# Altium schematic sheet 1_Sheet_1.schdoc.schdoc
size 495 x 241 mm; Name: A_A4; Symbol: A_A4; Device: A_A4; @Project Name: pupnik_2023-12-26_01-16-22; REV: 1.0; Date: 2023-12-25; Sheet: 1/1; Draw By: Penguin Kothe; Company: Your Company; Convert to PCB: yes; Add into BOM: yes
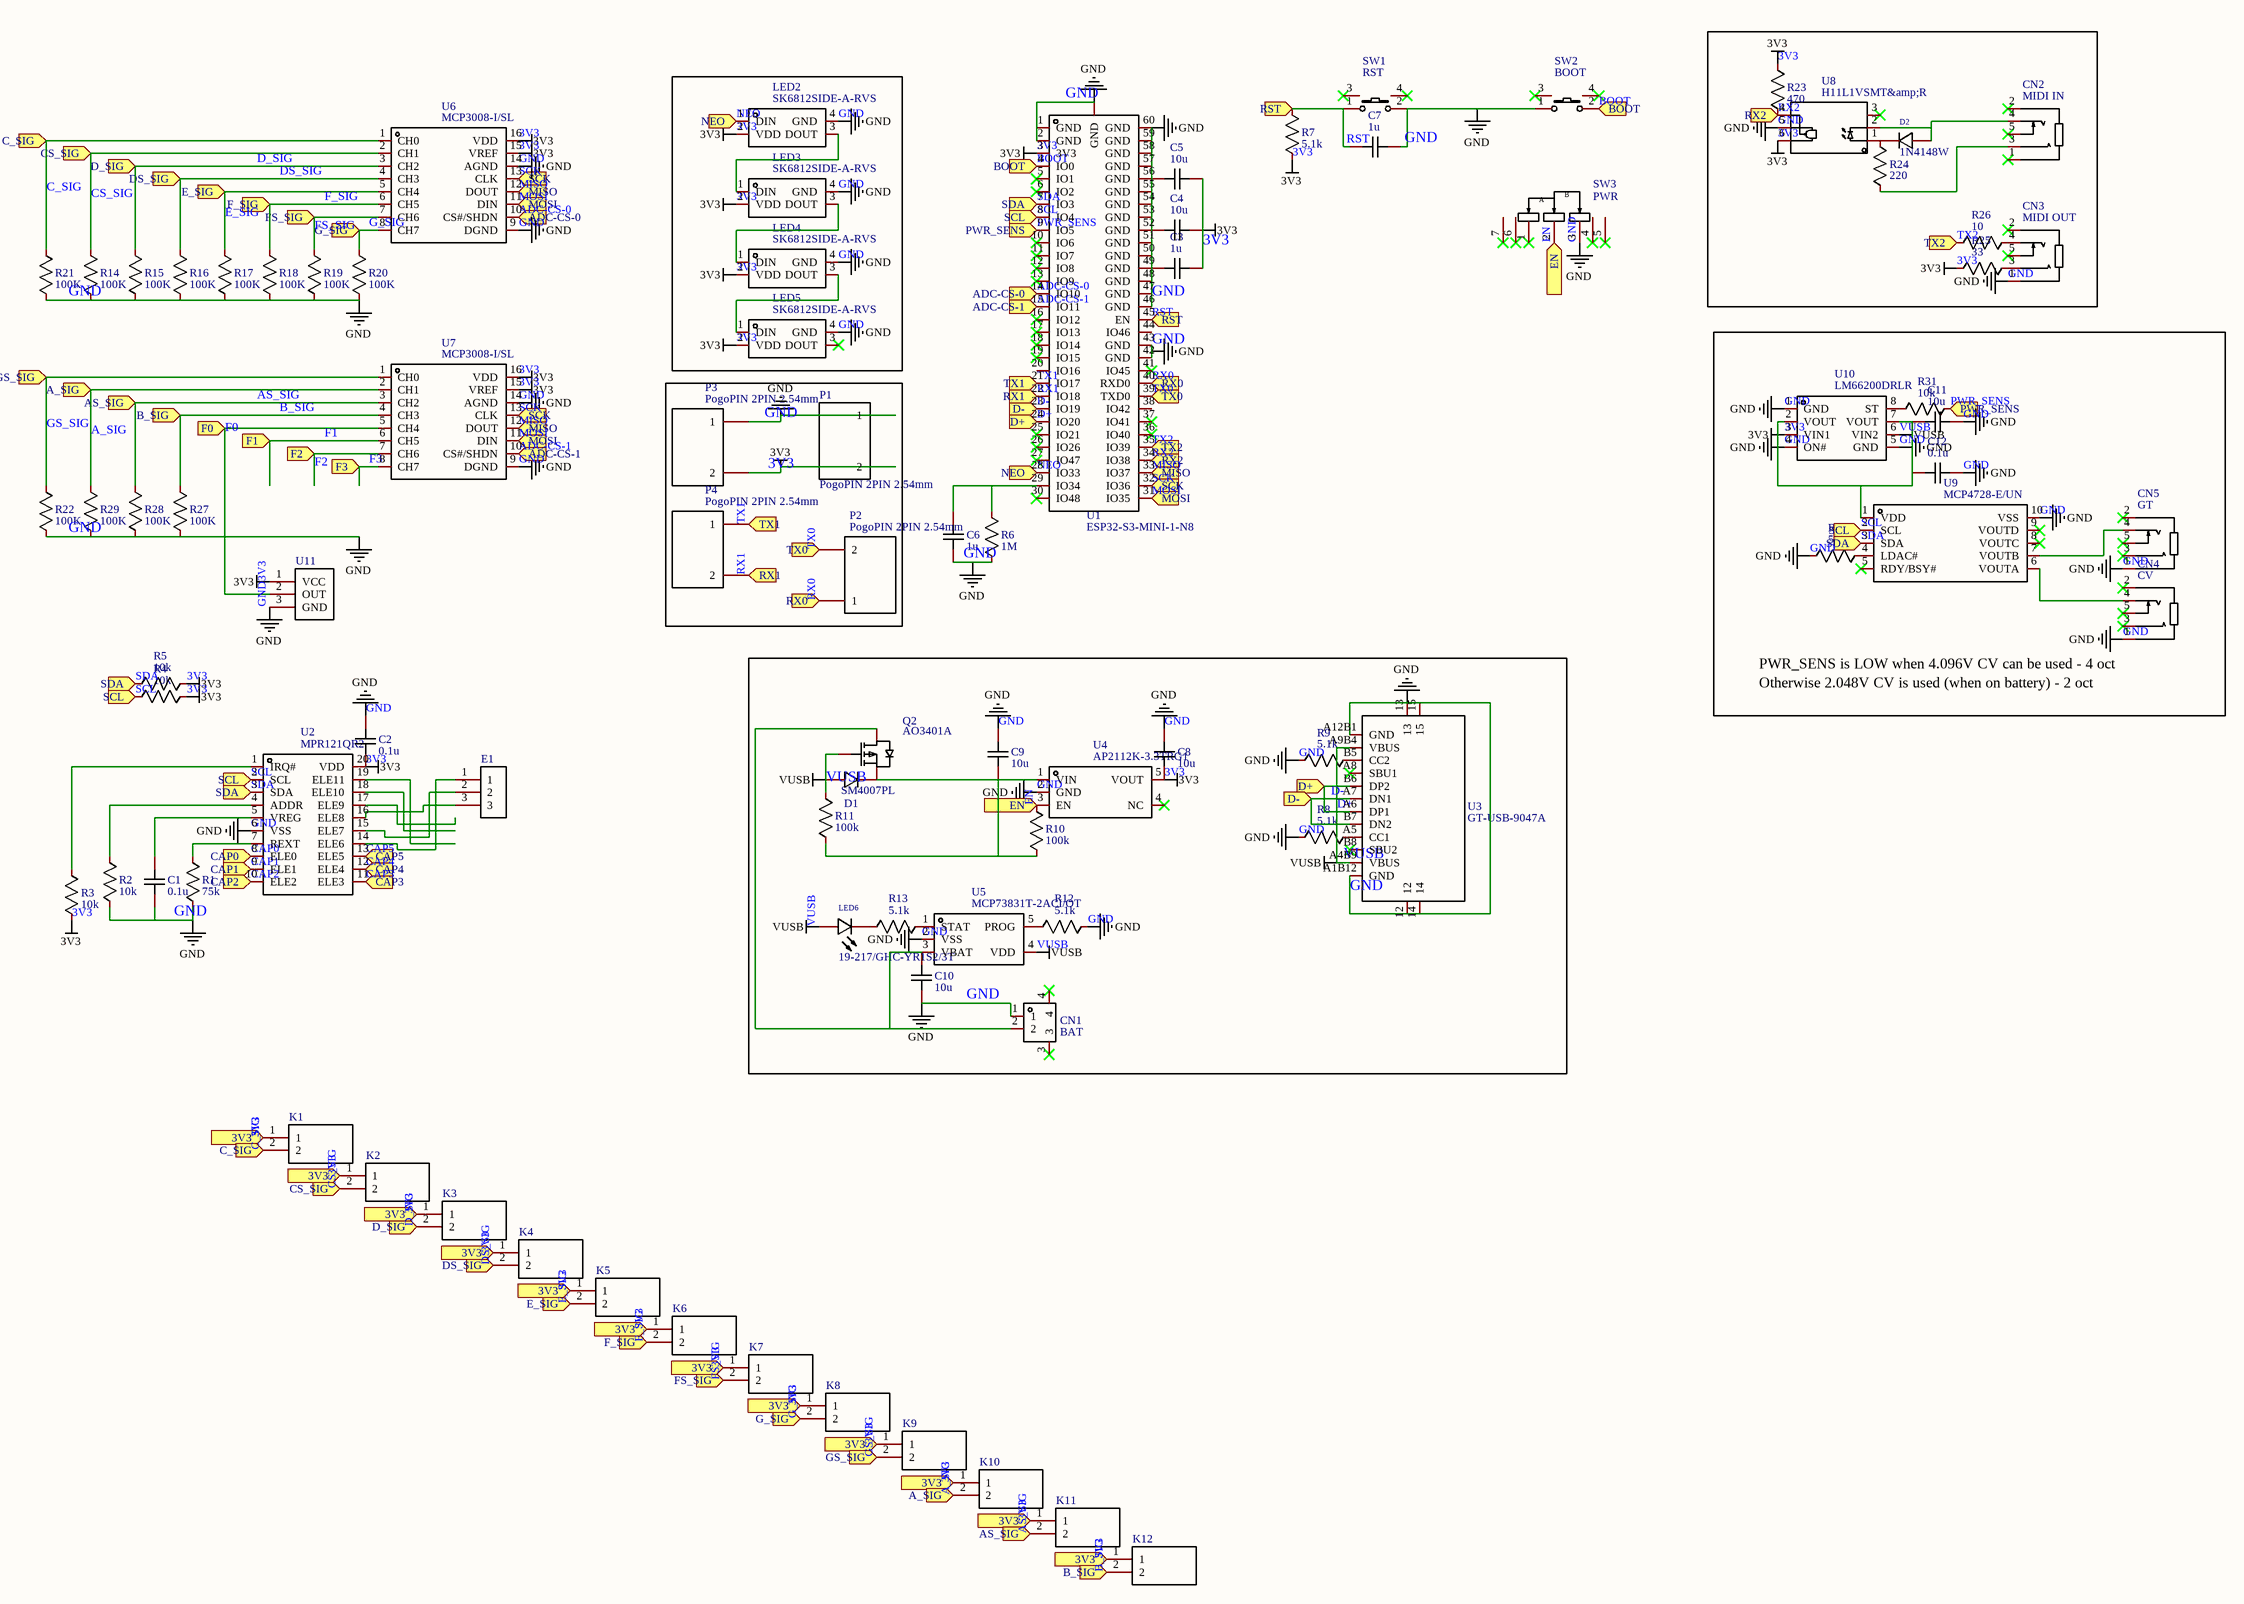
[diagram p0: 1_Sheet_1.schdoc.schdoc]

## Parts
C1  0.1u  [C0603]
C2  0.1u  [C0603]
C3  1u  [C0603]
C4  10u  [C0603]
C5  10u  [C0603]
C6  1u  [C0603]
C7  1u  [C0603]
C8  10u  [C0603]
C9  10u  [C0603]
C10  10u  [C0603]
C11  10u  [C0603]
C12  0.1u  [C0603]
CN1  BAT  [CONN-SMD_P2.00_S2B-PH-SM4-TB-LF-SN]
CN2  MIDI IN  [AUDIO-SMD_PJ-327A5JJ]
CN3  MIDI OUT  [AUDIO-SMD_PJ-327A5JJ]
CN4  CV  [AUDIO-SMD_PJ-327A5JJ]
CN5  GT  [AUDIO-SMD_PJ-327A5JJ]
D1  SM4007PL  [SOD-123F_L2.8-W1.8-LS3.7-RD]
D2  1N4148W  [SOD-123F_L2.7-W1.6-LS3.8-RD]
E1  enc  [enc]  (value not drawn)
K1  key  [key]  (value not drawn)
K2  key  [key]  (value not drawn)
K3  key  [key]  (value not drawn)
K4  key  [key]  (value not drawn)
K5  key  [key]  (value not drawn)
K6  key  [key]  (value not drawn)
K7  key  [key]  (value not drawn)
K8  key  [key]  (value not drawn)
K9  key  [key]  (value not drawn)
K10  key  [key]  (value not drawn)
K11  key  [key]  (value not drawn)
K12  key  [key]  (value not drawn)
LED2  SK6812SIDE-A-RVS  [LED-SMD_4P-L4.0-W1.6-L]
LED3  SK6812SIDE-A-RVS  [LED-SMD_4P-L4.0-W1.6-L]
LED4  SK6812SIDE-A-RVS  [LED-SMD_4P-L4.0-W1.6-L]
LED5  SK6812SIDE-A-RVS  [LED-SMD_4P-L4.0-W1.6-L]
LED6  19-217/GHC-YR1S2/3T  [LED0603-RD]
P1  PogoPIN 2PIN 2.54mm  [POGOPIN 2PIN 2.5MM]
P2  PogoPIN 2PIN 2.54mm  [POGOPIN 2PIN 2.5MM]
P3  PogoPIN 2PIN 2.54mm  [POGOPIN 2PIN 2.5MM]
P4  PogoPIN 2PIN 2.54mm  [POGOPIN 2PIN 2.5MM]
Q2  AO3401A  [SOT-23_L2.9-W1.3-P1.90-LS2.4-BR]
R1  75k  [R0603]
R2  10k  [R0603]
R3  10k  [R0603]
R4  10k  [R0603]
R5  10k  [R0603]
R6  1M  [R0603]
R7  5.1k  [R0603]
R8  5.1k  [R0603]
R9  5.1k  [R0603]
R10  100k  [R0603]
R11  100k  [R0603]
R12  5.1k  [R0603]
R13  5.1k  [R0603]
R14  100K  [R0603]
R15  100K  [R0603]
R16  100K  [R0603]
R17  100K  [R0603]
R18  100K  [R0603]
R19  100K  [R0603]
R20  100K  [R0603]
R21  100K  [R0603]
R22  100K  [R0603]
R23  470  [R0603]
R24  220  [R0603]
R25  33  [R0603]
R26  10  [R0603]
R27  100K  [R0603]
R28  100K  [R0603]
R29  100K  [R0603]
R30  5.1k  [R0603]
R31  10k  [R0603]
SW1  RST  [SW-SMD_L4.7-W3.5-P3.35-EH]
SW2  BOOT  [SW-SMD_L4.7-W3.5-P3.35-EH]
SW3  PWR  [SW-SMD_MK-12C02-G020]
U1  ESP32-S3-MINI-1-N8  [BULETM-SMD_ESP32-S3-MINI-1-N8]
U2  MPR121QR2  [QFN-20_L3.0-W3.0-P0.40-BL]
U3  GT-USB-9047A  [USB-C-SMD_GT-USB-9047A]
U4  AP2112K-3.3TRG1  [SOT-25-5_L2.9-W1.6-P0.95-LS2.8-BL]
U5  MCP73831T-2ACI/OT  [SOT-23-5_L3.0-W1.7-P0.95-LS2.8-BL]
U6  MCP3008-I/SL  [SOIC-16_L9.9-W3.9-P1.27-LS6.0-BL]
U7  MCP3008-I/SL  [SOIC-16_L9.9-W3.9-P1.27-LS6.0-BL]
U8  H11L1VSMT&amp;R  [SMD-6_L8.6-W6.4-P2.54-LS9.4-BL]
U9  MCP4728-E/UN  [MSOP-10_L3.0-W3.0-P0.50-LS5.0-TL]
U10  LM66200DRLR  [SOT-583-8_L2.1-W1.2-P0.50-LS1.6-BL]
U11  farts  [farts]  (value not drawn)

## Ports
3V3 (in), A_SIG (in), ADC-CS-0 (in), ADC-CS-1 (in), AS_SIG (in), B_SIG (in), BOOT (in), C_SIG (in), CAP0 (in), CAP1 (in), CAP2 (in), CAP3 (in), CAP4 (in), CAP5 (in), CS_SIG (in), D+ (in), D- (in), D_SIG (in), DS_SIG (in), E_SIG (in), EN (in), F0 (in), F1 (in), F2 (in), F3 (in), F_SIG (in), FS_SIG (in), G_SIG (in), GS_SIG (in), MISO (in), MOSI (in), NEO (in), PWR_SENS (in), RST (in), RX0 (in), RX1 (in), RX2 (in), SCK (in), SCL (in), SDA (in), TX0 (in), TX1 (in), TX2 (in)

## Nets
3V3: C2.1 C3.2 C4.2 C5.2 C8.1 K1.1 K2.1 K3.1 K4.1 K5.1 K6.1 K7.1 K8.1 K9.1 K10.1 K11.1 K12.1 LED2.2(VDD) LED3.2(VDD) LED4.2(VDD) LED5.2(VDD) P1.2 P3.2 R3.1 R4.1 R5.1 R7.1 R23.2 R25.2 U1.3(3V3) U2.20(VDD) U4.5(VOUT) U6.15(VREF) U6.16(VDD) U7.15(VREF) U7.16(VDD) U8.6(VCC) U10.3(VIN1) U11.1(VCC) ; port 3V3
D+: D1.2(A) LED6.2(A) Q2.1(G) R11.2 U1.24(IO20) U3.A4B9(VBUS) U3.A6(DP1) U3.A9B4(VBUS) U3.B6(DP2) U5.4(VDD) U10.6(VIN2) ; port D+  [also labelled VUSB]
GND: C1.1 C2.2 C3.1 C4.1 C5.1 C6.1 C7.2 C8.2 C9.2 C10.1 C11.1 C12.1 CN1.1 CN3.1 CN4.1 CN5.1 LED2.4(GND) LED3.4(GND) LED4.4(GND) LED5.4(GND) P1.1 P3.1 R1.1 R2.1 R6.1 R8.1 R9.1 R12.2 R14.1 R15.1 R16.1 R17.1 R18.1 R19.1 R20.1 R21.1 R22.1 R27.1 R28.1 R29.1 R30.1 SW1.2 SW2.1 SW3.3 U1.1(GND) U1.2(GND) U1.42(GND) U1.43(GND) U1.46(GND) U1.47(GND) U1.48(GND) U1.49(GND) U1.50(GND) U1.51(GND) U1.52(GND) U1.53(GND) U1.54(GND) U1.55(GND) U1.56(GND) U1.57(GND) U1.58(GND) U1.59(GND) U1.60(GND) U1.GND U2.6(VSS) U3.12 U3.13 U3.14 U3.15 U3.A1B12(GND) U3.A12B1(GND) U4.2(GND) U5.2(VSS) U6.9(DGND) U6.14(AGND) U7.9(DGND) U7.14(AGND) U8.5(GND) U9.10(VSS) U10.1(GND) U10.4(ON#) U10.5(GND) U11.3(GND)
A_SIG: K10.2 R29.2 U7.2(CH1) ; port A_SIG
ADC-CS-0: U1.14(IO10) U6.10(CS#/SHDN) ; port ADC-CS-0
ADC-CS-1: U1.15(IO11) U7.10(CS#/SHDN) ; port ADC-CS-1
AS_SIG: K11.2 R28.2 U7.3(CH2) ; port AS_SIG
B_SIG: K12.2 R27.2 U7.4(CH3) ; port B_SIG
BOOT: SW2.2 U1.4(IO0) ; port BOOT
C_SIG: K1.2 R21.2 U6.1(CH0) ; port C_SIG
CAP0: U2.8(ELE0) ; port CAP0
CAP1: U2.9(ELE1) ; port CAP1
CAP2: U2.10(ELE2) ; port CAP2
CAP3: U2.11(ELE3) ; port CAP3
CAP4: U2.12(ELE4) ; port CAP4
CAP5: U2.13(ELE5) ; port CAP5
CS_SIG: K2.2 R14.2 U6.2(CH1) ; port CS_SIG
D-: U1.23(IO19) U3.A7(DN1) U3.B7(DN2) ; port D-
D_SIG: K3.2 R15.2 U6.3(CH2) ; port D_SIG
DS_SIG: K4.2 R16.2 U6.4(CH3) ; port DS_SIG
E_SIG: K5.2 R17.2 U6.5(CH4) ; port E_SIG
EN: R10.2 SW3.2 U4.3(EN) ; port EN
F0: U7.5(CH4) U11.2(OUT) ; port F0
F1: U7.6(CH5) ; port F1
F2: U7.7(CH6) ; port F2
F3: U7.8(CH7) ; port F3
F_SIG: K6.2 R18.2 U6.6(CH5) ; port F_SIG
FS_SIG: K7.2 R19.2 U6.7(CH6) ; port FS_SIG
G_SIG: K8.2 R20.2 U6.8(CH7) ; port G_SIG
GS_SIG: K9.2 R22.2 U7.1(CH0) ; port GS_SIG
MISO: U1.33(IO37) U6.12(DOUT) U7.12(DOUT) ; port MISO
MOSI: U1.31(IO35) U6.11(DIN) U7.11(DIN) ; port MOSI
NEO: LED2.1(DIN) U1.28(IO33) ; port NEO
PWR_SENS: R31.2 U1.9(IO5) ; port PWR_SENS
RST: C7.1 R7.2 SW1.1 U1.45(EN) ; port RST
RX0: P2.1 U1.40(RXD0) ; port RX0
RX1: P4.2 U1.22(IO18) ; port RX1
RX2: R23.1 U1.34(IO38) U8.4(VO) ; port RX2
SCK: U1.32(IO36) U6.13(CLK) U7.13(CLK) ; port SCK
SCL: R4.2 U1.8(IO4) U2.2(SCL) U9.2(SCL) ; port SCL
SDA: R5.2 U1.7(IO3) U2.3(SDA) U9.3(SDA) ; port SDA
TX0: P2.2 U1.39(TXD0) ; port TX0
TX1: P4.1 U1.21(IO17) ; port TX1
TX2: R26.2 U1.35(IO39) ; port TX2
NetC1_2: C1.2 U2.5(VREG)
NetC6_2: C6.2 R6.2 U1.29(IO34)
NetC9_1: C9.1 D1.1(C) Q2.2(S) R10.1 R11.1 U4.1(VIN)
NetC10_2: C10.2 CN1.2 Q2.3(D) U5.3(VBAT)
NetC11_2: C11.2 C12.2 U9.1(VDD) U10.2(VOUT) U10.7(VOUT)
NetCN2_3: CN2.3 R24.1
NetCN2_4: CN2.4 D2.2(A) U8.2(C)
NetCN3_3: CN3.3 R25.1
NetCN3_4: CN3.4 R26.1
NetCN4_4: CN4.4 U9.6(VOUTA)
NetCN5_4: CN5.4 U9.7(VOUTB)
NetD2_1: D2.1(K) R24.2 U8.1(A)
NetE1_1: E1.1 U2.14(ELE6)
NetE1_2: E1.2 U2.15(ELE7)
NetE1_3: E1.3 U2.16(ELE8)
NetLED2_3: LED2.3(DOUT) LED3.1(DIN)
NetLED3_3: LED3.3(DOUT) LED4.1(DIN)
NetLED4_3: LED4.3(DOUT) LED5.1(DIN)
NetLED6_1: LED6.1(C) R13.1
NetR1_2: R1.2 U2.7(REXT)
NetR2_2: R2.2 U2.4(ADDR)
NetR3_2: R3.2 U2.1(IRQ#)
NetR8_2: R8.2 U3.A5(CC1)
NetR9_2: R9.2 U3.B5(CC2)
NetR12_1: R12.1 U5.5(PROG)
NetR13_2: R13.2 U5.1(STAT)
NetR30_2: R30.2 U9.4(LDAC#)
NetR31_1: R31.1 U10.8(ST)

Not connected (* = marked no-connect by the designer): CN1 3* 4*; CN2 1* 2* 5*; CN3 2* 5*; CN4 2* 3* 5*; CN5 2* 3* 5*; LED5 3(DOUT)*; SW1 3* 4*; SW2 3* 4*; SW3 1* 4* 5* 6* 7*; U1 5(IO1)* 6(IO2)* 10(IO6)* 11(IO7)* 12(IO8)* 13(IO9)* 16(IO12)* 17(IO13)* 18(IO14)* 19(IO15)* 20(IO16) 25(IO21)* 26(IO26)* 27(IO47)* 30(IO48)* 36(IO40)* 37(IO41)* 38(IO42) 41(IO45)* 44(IO46); U2 17(ELE9) 18(ELE10) 19(ELE11); U3 A8(SBU1)* B8(SBU2)*; U4 4(NC)*; U8 3(NC)*; U9 5(RDY/BSY#)* 8(VOUTC)* 9(VOUTD)*

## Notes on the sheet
- (near CN4) PWR_SENS is LOW when 4.096V CV can be used - 4 oct
- (near CN4) Otherwise 2.048V CV is used (when on battery) - 2 oct

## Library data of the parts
C1 C2 C12 = 0.1u: Convert to PCB: yes
C3 C6 C7 = 1u: Convert to PCB: yes
C4 C5 C8-C11 = 10u: Convert to PCB: yes
CN1 = BAT: Manufacturer: JST; Manufacturer Part: S2B-PH-SM4-TB(LF)(SN); Convert to PCB: yes
CN2 = MIDI IN: Manufacturer: SHOU HAN(首韩); Manufacturer Part: PJ-327A 5JJ; Convert to PCB: yes
CN3 = MIDI OUT: Manufacturer: SHOU HAN(首韩); Manufacturer Part: PJ-327A 5JJ; Convert to PCB: yes
CN4 = CV: Manufacturer: SHOU HAN(首韩); Manufacturer Part: PJ-327A 5JJ; Convert to PCB: yes
CN5 = GT: Manufacturer: SHOU HAN(首韩); Manufacturer Part: PJ-327A 5JJ; Convert to PCB: yes
D1 = SM4007PL: Manufacturer: MDD; Convert to PCB: yes
D2 = 1N4148W_C81598: Diode Configuration: Forward Voltage (Vf@If):1V@50mA Reverse Voltage (Vr): Average Rectified Current (Io): Power Dissipation: Reverse Leakage Current:1uA@75V Reverse Recovery Time (trr): Operating Temperature:- Operating Temperature:-; Manufacturer: ST(先科); Add into BOM: yes
E1 = enc: Add into BOM: yes
K1-K12 = key: Add into BOM: yes
LED2-LED5 = SK6812SIDE-A-RVS: Manufacturer: 欧思科光电; Convert to PCB: yes
LED6 = 19-217/GHC-YR1S2/3T: Emitted Color:Emerald Diode Configuration:- Forward Voltage (VF):3.3V Forward Voltage (VF):3.3V Forward Current:20mA Power Dissipation:110mW Lens Color:无色透明透镜 Dominant Wavelength:520nm~535nm Dominant Wavelength:520nm~535nm Peak Wavelength:518nm Color Temp; Manufacturer: EVERLIGHT(亿光); Add into BOM: yes; Forward Voltage (VF): 3.3V; Forward Current: 20mA; Power Dissipation: 110mW; Lens Color: 无色透明透镜; Peak Wavelength: 518nm; Luminous Intensity: 199mcd; Viewing Angle: 120°
P1-P4 = PogoPIN 2PIN 2.54mm: Convert to PCB: yes
Q2 = AO3401A_C15127: Type: Drain Source Voltage (Vdss): Continuous Drain Current (Id): Power Dissipation (Pd): Drain Source On Resistance (RDS(on)@Vgs,Id):44mΩ@10V,4.3A Gate Threshold Voltage (Vgs(th)@Id):1.3V@250uA; Manufacturer: AOS; Add into BOM: yes
R1 = 75k: Convert to PCB: yes
R2-R5 R31 = 10k: Convert to PCB: yes
R6 = 1M: Convert to PCB: yes
R7-R9 R12 R13 R30 = 5.1k: Convert to PCB: yes
R10 R11 = 100k: Convert to PCB: yes
R14-R22 R27-R29 = 100K: Convert to PCB: yes
R23 = 470: Convert to PCB: yes
R24 = 220: Convert to PCB: yes
R25 = 33: Convert to PCB: yes
R26 = 10: Convert to PCB: yes
SW1 = RST: Manufacturer: SHOU HAN(首韩); Manufacturer Part: TS24CA 250gf 013; Convert to PCB: yes
SW2 = BOOT: Manufacturer: SHOU HAN(首韩); Manufacturer Part: TS24CA 250gf 013; Convert to PCB: yes
SW3 = MK-12C02-G020: Manufacturer: G-Switch(品赞); Add into BOM: yes
U1 = ESP32-S3-MINI-1-N8: Manufacturer: ESPRESSIF(乐鑫); Convert to PCB: yes
U2 = MPR121QR2: Manufacturer: NXP(恩智浦); Convert to PCB: yes
U3 = GT-USB-9047A: Manufacturer: G-Switch(品赞); Convert to PCB: yes
U4 = AP2112K-3.3TRG1: Manufacturer: DIODES(美台); Convert to PCB: yes
U5 = MCP73831T-2ACI/OT: Manufacturer: MICROCHIP(美国微芯); Convert to PCB: yes
U6 U7 = MCP3008-I/SL: Manufacturer: MICROCHIP(美国微芯); Convert to PCB: yes
U8 = H11L1VSMT&amp;R: Manufacturer: ISOCOM(英国安数光); Symbol: H11L1VSMT&amp;amp;R; Convert to PCB: yes
U9 = MCP4728-E/UN: Manufacturer: MICROCHIP(美国微芯); Convert to PCB: yes
U10 = LM66200DRLR: Manufacturer: TI(德州仪器); Convert to PCB: yes
U11 = farts: Add into BOM: yes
